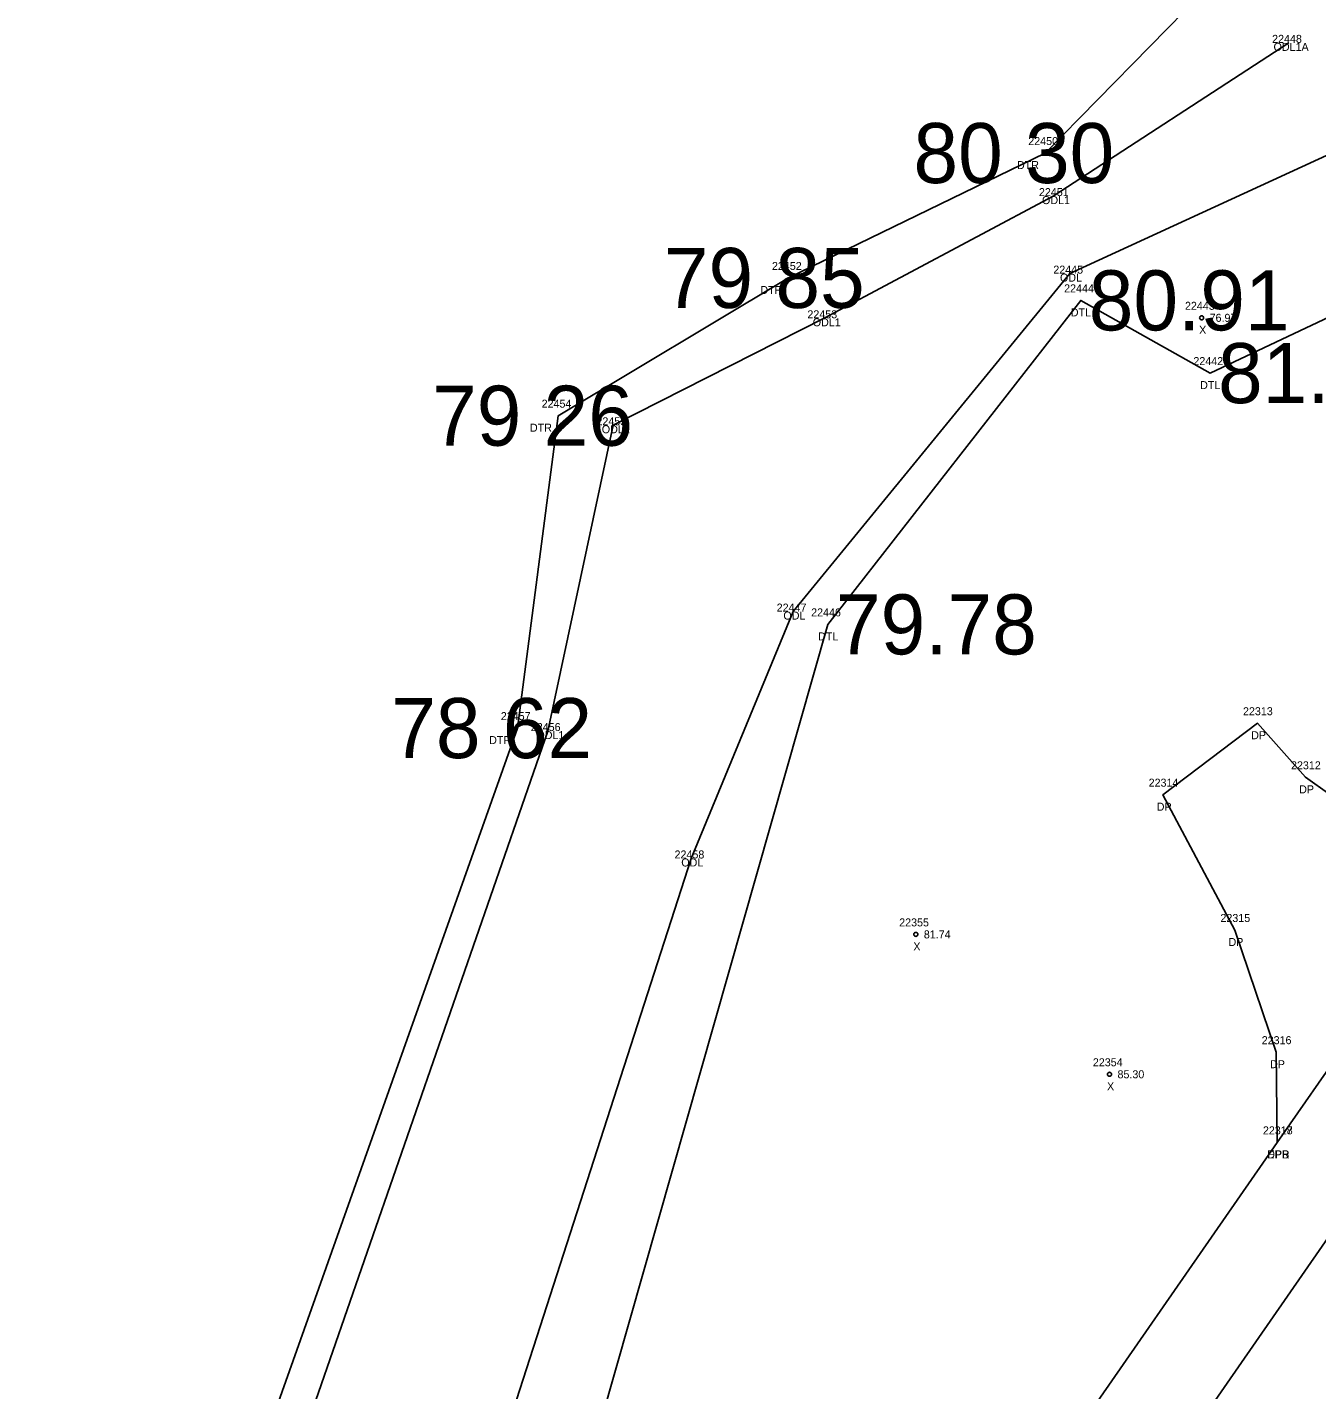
# Model space of a CAD drawing. Extents: x 2266664 to 2272385, y 716533 to 724777.
# Drawn here: x 2270853 to 2271014.2, y 722788.6 to 722958.8 of the extents above; entities that cross this region are included whole.
import ezdxf

# ---------------------------------------------------------------- set-up
doc = ezdxf.new("R2010")
doc.units = 0
for name, color, linetype in [('RD_DTM_BkLn1', 7, 'Continuous'), ('RD_EX_DR_Inlet_txCode', 7, 'Continuous'), ('RD_EX_Driveway', 7, 'Continuous'), ('RD_EX_Driveway_txCode', 7, 'Continuous'), ('RD_EX_H2O', 7, 'Continuous'), ('RD_EX_H2O_txCode', 7, 'Continuous'), ('RD_EX_Road', 7, 'Continuous'), ('RD_EX_Road_txCode', 7, 'Continuous'), ('RD_Sketch8', 7, 'Continuous'), ('RD_SMD_Locator', 7, 'Continuous')]:
    doc.layers.add(name, color=color, linetype=linetype)

msp = doc.modelspace()

# ---------------------------------------------------------------- linework, layer by layer
at = {"layer": 'RD_DTM_BkLn1'}
msp.add_lwpolyline([(2271071.9, 722890), (2271022.74, 722818.33), (2271016.63, 722809.08), (2270958.33, 722725.01), (2270901.32, 722642.18), (2270840.59, 722553.52), (2270785.24, 722472.83), (2270728.9, 722390.97), (2270676.09, 722314.01), (2270618.86, 722231.46), (2270562.47, 722149.97), (2270509.04, 722072.31)], dxfattribs=at)
at = {"layer": 'RD_EX_Driveway'}
msp.add_lwpolyline([(2271034.11, 722857.81), (2271024.92, 722856.45), (2271012.76, 722865.1), (2271006.76, 722871.86), (2270994.96, 722862.93), (2271003.93, 722846.02), (2271009.12, 722830.75), (2271009.25, 722819.48)], dxfattribs=at)
at = {"layer": 'RD_EX_H2O'}
for points in [[(2270999.84, 722963.15), (2270980.25, 722943.11), (2270948.18, 722927.5), (2270919.39, 722910.29), (2270914.3, 722871.25), (2270880.51, 722776), (2270826.19, 722691.33), (2270767.96, 722609.51), (2270709.2, 722523.56), (2270655.82, 722445.77), (2270599.29, 722364.14), (2270544.36, 722283.47), (2270486.41, 722202.72), (2270437.65, 722128.66), (2270381.61, 722049.14), (2270312.65, 721946.45), (2270267.02, 721881.66), (2270199.49, 721783.94), (2270145.55, 721706.24)], [(2271010.68, 722956.88), (2270981.26, 722937.73), (2270952.61, 722922.46), (2270926.25, 722909.09), (2270918.08, 722870.88), (2270884.06, 722772.73), (2270830.33, 722688.86), (2270771.05, 722606.35), (2270712.53, 722520.24), (2270659.86, 722442.81), (2270604.09, 722362.46), (2270549.07, 722281.09), (2270493.85, 722201.63), (2270442.11, 722125.25), (2270388.24, 722045.96), (2270316.35, 721943.79), (2270270.36, 721877.08), (2270205.08, 721780.4), (2270149.38, 721703.27)], [(2271023.5, 722946.55), (2270983.34, 722928.04), (2270948.77, 722885.81), (2270936.01, 722854.96), (2270907.81, 722767.63), (2270849.93, 722675.41), (2270794.17, 722593.77), (2270730.31, 722507.93), (2270678, 722428.57), (2270622.95, 722348.52), (2270567.11, 722264.74), (2270510.62, 722184.83), (2270454.97, 722112.23), (2270398.62, 722023.73), (2270335.52, 721936.71), (2270280.46, 721850.25), (2270222.76, 721771.51), (2270169.39, 721696.38), (2270111.35, 721612), (2270050.32, 721526.8), (2269987.94, 721437.31), (2269982.52, 721401.11), (2269986.76, 721385.77), (2270012.24, 721386.18)], [(2271033.41, 722941.96), (2271017.26, 722923.37), (2271000.84, 722915.61), (2270984.69, 722924.7), (2270953.1, 722884.21), (2270916.86, 722756.99), (2270859.77, 722671.98), (2270798.36, 722591.12), (2270738.02, 722501.89), (2270682.59, 722424.89), (2270629.35, 722346.56), (2270572.53, 722262.27), (2270515.87, 722180.88), (2270459.66, 722106.47), (2270403.98, 722020.3), (2270343.58, 721932.89), (2270284.34, 721846.17), (2270230.48, 721766.75), (2270175.19, 721692.18), (2270115.51, 721607.69), (2270056.41, 721522.72), (2269992.94, 721435.27), (2269987.18, 721402.63)]]:
    msp.add_lwpolyline(points, dxfattribs=at)
at = {"layer": 'RD_EX_Road'}
msp.add_lwpolyline([(2271062.22, 722896.9), (2271050.1, 722878.52), (2271035.36, 722856.97), (2271009.25, 722819.48), (2270948.68, 722732.14), (2270891.73, 722649.3), (2270830.29, 722559.72), (2270774.71, 722479.03), (2270718.54, 722397.26), (2270665.83, 722320.36), (2270608.79, 722237.92), (2270552.34, 722156.58), (2270498.7, 722078.55)], dxfattribs=at)
at = {"layer": 'RD_SMD_Locator'}
for centre, radius in [((2271010.68, 722956.88), 0.001), ((2270980.25, 722943.11), 0.001), ((2270981.26, 722937.73), 0.001), ((2270948.18, 722927.5), 0.001), ((2270983.34, 722928.04), 0.001), ((2270984.69, 722924.7), 0.001), ((2270952.61, 722922.46), 0.001), ((2270999.79, 722922.52), 0.25), ((2271000.84, 722915.61), 0.001), ((2270919.39, 722910.29), 0.001), ((2270926.25, 722909.09), 0.001), ((2270948.77, 722885.81), 0.001), ((2270953.1, 722884.21), 0.001), ((2270914.3, 722871.25), 0.001), ((2270918.08, 722870.88), 0.001), ((2271006.76, 722871.86), 0.001), ((2271012.76, 722865.1), 0.001), ((2270994.96, 722862.93), 0.001), ((2270936.01, 722854.96), 0.001), ((2270964.08, 722845.47), 0.25), ((2271003.93, 722846.02), 0.001), ((2271009.12, 722830.75), 0.001), ((2270988.28, 722827.99), 0.25), ((2271009.25, 722819.48), 0.001), ((2271009.25, 722819.48), 0.001)]:
    msp.add_circle(centre, radius, dxfattribs=at)

# ---------------------------------------------------------------- texts
at = {"layer": 'RD_EX_DR_Inlet_txCode'}
for s, p in [('80 30', (2270963.78, 722939.36)), ('79 85', (2270932.59, 722923.75)), ('80.91', (2270985.69, 722920.95)), ('81.02', (2271001.84, 722911.86)), ('79 26', (2270903.63, 722906.54)), ('79.78', (2270954.1, 722880.46)), ('78 62', (2270898.53, 722867.5))]:
    msp.add_text(s, height=7.5, dxfattribs=at).set_placement(p)
at = {"layer": 'RD_EX_Driveway_txCode'}
for s, p in [('22313', (2271004.96, 722872.86)), ('DP', (2271005.98, 722869.86)), ('22312', (2271010.96, 722866.1)), ('22314', (2270993.17, 722863.93)), ('DP', (2271011.98, 722863.1)), ('DP', (2270994.18, 722860.93)), ('22315', (2271002.14, 722847.02)), ('DP', (2271003.15, 722844.02)), ('22316', (2271007.3, 722831.75)), ('DP', (2271008.34, 722828.75)), ('22317', (2271007.45, 722820.48)), ('DPB', (2271007.99, 722817.48))]:
    msp.add_text(s, height=1, dxfattribs=at).set_placement(p)
at = {"layer": 'RD_EX_H2O_txCode'}
for s, p in [('22448', (2271008.6, 722956.88)), ('ODL1A', (2271008.78, 722955.88)), ('22450', (2270978.13, 722944.11)), ('DTR', (2270976.72, 722941.11)), ('22451', (2270979.46, 722937.73)), ('ODL1', (2270979.85, 722936.73)), ('22452', (2270946.1, 722928.5)), ('22445', (2270981.26, 722928.04)), ('DTR', (2270944.65, 722925.5)), ('ODL', (2270982.09, 722927.04)), ('22444', (2270982.61, 722925.7)), ('22453', (2270950.53, 722922.46)), ('DTL', (2270983.44, 722922.7)), ('ODL1', (2270951.2, 722921.46)), ('22442', (2270998.76, 722916.61)), ('DTL', (2270999.6, 722913.61)), ('22454', (2270917.32, 722911.29)), ('22455', (2270924.17, 722909.09)), ('DTR', (2270915.86, 722908.29)), ('ODL1', (2270924.84, 722908.09)), ('22447', (2270946.69, 722885.81)), ('ODL', (2270947.53, 722884.81)), ('22446', (2270951, 722885.21)), ('DTL', (2270951.86, 722882.21)), ('22457', (2270912.22, 722872.25)), ('22456', (2270915.97, 722870.88)), ('ODL1', (2270916.67, 722869.88)), ('DTR', (2270910.76, 722869.25)), ('22458', (2270933.93, 722854.96)), ('ODL', (2270934.77, 722853.96))]:
    msp.add_text(s, height=1, dxfattribs=at).set_placement(p)
at = {"layer": 'RD_EX_Road_txCode'}
for s, p in [('22318', (2271007.45, 722820.48)), ('EPR', (2271008.02, 722817.48))]:
    msp.add_text(s, height=1, dxfattribs=at).set_placement(p)
at = {"layer": 'RD_Sketch8'}
for s, p in [('22443', (2270997.71, 722923.52)), ('X', (2270999.48, 722920.52)), ('76.97', (2271000.79, 722922.02)), ('22355', (2270962, 722846.47)), ('81.74', (2270965.08, 722844.97)), ('X', (2270963.77, 722843.47)), ('22354', (2270986.2, 722828.99)), ('85.30', (2270989.28, 722827.49)), ('X', (2270987.97, 722825.99))]:
    msp.add_text(s, height=1, dxfattribs=at).set_placement(p)

doc.saveas('drawing.dxf')
